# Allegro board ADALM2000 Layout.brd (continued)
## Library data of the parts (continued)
C8 C14 C20-C22 C24-C28 C94 C217 C218 C258-C261 C270 C271 C281 C302-C305 C314 C315 C596 C607 C615 C639 C641 C665 C666 C672 C675 C679 C698-C701 C789 = CAP: Tolerance: 10; User Part Number: UPN; alternate symbols: C0402L_ALT; part number: CAP_SM-4.7UF,10V,10,E022491,C0402; tolerance: 10
C9-C12 = CAP: Tolerance: 20; User Part Number: UPN; alternate symbols: (); part number: CAP_SM-47UF,10V,20,E020003,C1206H71; tolerance: 20
C13 C34-C43 C45 C46 C48 C70 C78 C83 C84 C93 C102 C117-C120 C127 C135 C140 C141 C149 C153 C168-C171 C188 C225 C227 C233-C235 C253 C254 C268 C269 C276 C277 C282 C283 C290 C295 C298 C301 C309 C322 C323 C328 C332 C335 C599 C633 C644 C648 C650 C654 C660 C692 C712 C713 C793 C803 = CAP: User Part Number: UPN; Tolerance: 10; alternate symbols: (); part number: CAP_SM-0.01UF,25V,10,E022720,C0201; tolerance: 10
C15 = CAP: Tolerance: 10; User Part Number: UPN; alternate symbols: C0402L_ALT; part number: CAP_SM-15NF,35V,10,E033385,C0402; tolerance: 10
C17 C122 C173 = CAP: Tolerance: 5; User Part Number: UPN; alternate symbols: C0402L_ALT; part number: CAP_SM-10PF,50V,5,E007982,C0402; tolerance: 5
C18 C105 C106 C154 C155 C176 C178 C183 C187 C190 C226 C230 C242 C243 C278 C279 C289 C291 C312 C313 C325 C326 C656 C659 C662 C737 C738 C740 C742 C769 C774 = CAP: Tolerance: 20; User Part Number: UPN; alternate symbols: C0603L_ALT; part number: CAP_SM-10UF,10V,20,E022682,C0603; tolerance: 20
C23 C99 = CAP: User Part Number: UPN; Tolerance: 20; alternate symbols: C0805-2; part number: CAP_SM-22UF,25V,20,E032575,C0805H60; tolerance: 20
C52 = CAP: Tolerance: 10; User Part Number: UPN; alternate symbols: C0402L_ALT; part number: CAP_SM-1000PF,25V,10,E025706,C0402; tolerance: 10
C63 C657 = CAP: Tolerance: 10; User Part Number: UPN; alternate symbols: C0402L_ALT; part number: CAP_SM-0.22UF,16V,10,E032715,C0402; tolerance: 10
C64 = CAP: Tolerance: 5; User Part Number: UPN; alternate symbols: C0402L_ALT; part number: CAP_SM-820PF,25V,5,E012598,C0402; tolerance: 5
C66 = CAP: Tolerance: 10; User Part Number: UPN; alternate symbols: C0402L_ALT; part number: CAP_SM-0.068UF,10V,10,E033177,C0402H22; tolerance: 10
C69 C71 C126 C128 = CAPVAR: Tolerance: N/A; User Part Number: UPN; alternate symbols: (); part number: CAPVAR_SM-5-20PF,100V,N/A,E023860,CSML177W126H67; tolerance: N/A
C72 C75 C129 C132 C182 C197 = CAP: Tolerance: 5; User Part Number: UPN; alternate symbols: C0603L_ALT; part number: CAP_SM-33PF,50V,5,E000396,C0603; tolerance: 5
C73 C76 C95 C130 = CAP: Tolerance: 5; User Part Number: UPN; alternate symbols: C0603L_ALT; part number: CAP_SM-82PF,50V,5,E000414,C0603; tolerance: 5
C74 C77 C131 C134 = CAP: Tolerance: 2; User Part Number: UPN; alternate symbols: C0603L_ALT; part number: CAP_SM-0.001UF,50V,2,E022455,C0603; tolerance: 2
C85 C88 C143 C145 C236 C237 = CAP: Tolerance: 5; User Part Number: UPN; alternate symbols: C0402L_ALT; part number: CAP_SM-100PF,50V,5,E024302,C0402; tolerance: 5; signal model: capacitor20pF
C89 C92 C146 C147 C751 = CAP: Tolerance: 5; User Part Number: UPN; alternate symbols: C0402L_ALT; part number: CAP_SM-150PF,50V,5,E012646,C0402; tolerance: 5
C101 = CAP: Tolerance: 20; User Part Number: UPN; alternate symbols: C0805-2; part number: CAP_SM-22UF,25V,20,E032575,C0805H60; tolerance: 20
C103 C104 C121 C123 C162 C163 C172 C174 C266 C267 = CAP: Tolerance: 0.1pF; User Part Number: UPN; alternate symbols: C0402L_ALT; part number: CAP_SM-1PF,25V,0.1PF,E011093,C0402; tolerance: 0.1pF
C181 C189 C337 C339 = CAP: User Part Number: UPN; Tolerance: 0.05PF; alternate symbols: (); part number: CAP_SM-3PF,50V,0.05PF,E033791,C0402; tolerance: 0.05PF
C184 C238 = CAP: Tolerance: 5; User Part Number: UPN; alternate symbols: C0402L_ALT; part number: CAP_SM-220PF,50V,5,E018153,C0402; tolerance: 5
C185 C336 C338 C340 = CAP: User Part Number: UPN; Tolerance: 0.25PF; alternate symbols: (); part number: CAP_SM-1PF,50V,0.25PF,E000276,C0402; tolerance: 0.25PF
C193 C194 C745 C746 = CAP: Tolerance: 10; User Part Number: UPN; alternate symbols: C0402L_ALT; part number: CAP_SM-0.047UF,25V,10,E025704,C0402; tolerance: 10
C199 = CAP: Tolerance: 5; User Part Number: UPN; alternate symbols: C0402L_ALT; part number: CAP_SM-120PF,25V,5,E012600,C0402; tolerance: 5
C200 C201 = CAP: Tolerance: 10; User Part Number: UPN; alternate symbols: C0402L_ALT; part number: CAP_SM-0.018UF,16V,10,E019653,C0402; tolerance: 10
C203 = CAP: Tolerance: 10; User Part Number: UPN; alternate symbols: C0402L_ALT; part number: CAP_SM-0.0022UF,50V,10,E007460,C0402; tolerance: 10
C207 = CAP: Tolerance: 5; User Part Number: UPN; alternate symbols: C0402L_ALT; part number: CAP_SM-0.0012UF,25V,5,E012597,C0402; tolerance: 5
C208 C241 C320 C321 C664 C678 C680 C696 C697 C754 C758 C761 C762 = CAP: Tolerance: 20; User Part Number: UPN; alternate symbols: (C0805L); part number: CAP_SM-47UF,6.3V,20,E008247,C0805H60; tolerance: 20
C223 = CAP: User Part Number: UPN; Tolerance: 1; alternate symbols: (); part number: CAP_SM-12PF,50V,1,E033792,C0402; tolerance: 1
C239 = CAP: Tolerance: 0.05pF; User Part Number: UPN; alternate symbols: C0402L_ALT; part number: CAP_SM-4.7PF,50V,0.05PF,E021938,C0402; tolerance: 0.05pF
C248 C249 C252 C255-C257 = CAP: Tolerance: 0.1pF; User Part Number: UPN; alternate symbols: C0402L_ALT; part number: CAP_SM-3.9PF,50V,0.1PF,E014597,C0402; tolerance: 0.1pF
C280 C801 = CAP: Tolerance: 10; User Part Number: UPN; alternate symbols: C0402L_ALT; part number: CAP_SM-2.2UF,10V,10,E017584,C0402; tolerance: 10
C327 C329 = CAP: User Part Number: UPN; Tolerance: 20; alternate symbols: C0402L_ALT; part number: CAP_SM-1UF,16V,20,E020695,C0402; tolerance: 20
C579 C588 C589 C598 C626 C647 C649 C651 C652 C655 C658 C688 C710 C711 C792 C795 = CAP: User Part Number: UPN; Tolerance: 20; part number: CAP_SM-0.1UF,16V,20,E017331,C0201; tolerance: 20
C595 C600 C637 C663 C670 C676 C788 = CAP: Tolerance: 20; User Part Number: UPN; alternate symbols: (); part number: CAP_SM-100UF,6.3V,20,E016591,C1206H71; tolerance: 20
C597 C614 C616-C618 C643 C645 C667-C669 C671 C673 C674 C683 C684 C686 C702-C709 C790 = CAP: Tolerance: 10; User Part Number: UPN; alternate symbols: C0402L_ALT; part number: CAP_SM-0.47UF,10V,10,E007611,C0402; tolerance: 10
C753 = CAP: Tolerance: 5; User Part Number: UPN; alternate symbols: C0402L_ALT; part number: CAP_SM-5.6NF,50V,5,E033450,C0402H22; tolerance: 5
C756 = CAP: Tolerance: 5; User Part Number: UPN; alternate symbols: C0402L_ALT; part number: CAP_SM-180PF,50V,5,E033222,C0402; tolerance: 5
C757 = CAP: Tolerance: 10; User Part Number: UPN; alternate symbols: C0402L_ALT; part number: CAP_SM-0.0033UF,50V,10,E007461,C0402; tolerance: 10
CALIB_REF1 CALIB_REF2 GND_7-GND_10 IO3 RX TCK TDI TDO TMS TX UNK1V8_D UNK1V35 UNK3V3_A UNK3V3_D UNK4V0_A UNK6V0_A UNK-3V3_A UNK-6V0_A VCCPINT VIN = NCTESTPAD: Tolerance: N/A; User Part Number: UPN; alternate symbols: (); part number: NCTESTPAD_SM-TESTPAD,E019801,TPSMC40; tolerance: N/A
D1 D26 = DIOZNR: User Part Number: UPN; Tolerance: 5; alternate symbols: (); part number: DIOZNR_SM-SMBJ5340B-TP,6V,5,E029884,DO214AA; tolerance: 5
D2-D23 = DIO3P_V3: Tolerance: N/A; User Part Number: UPN; alternate symbols: (); part number: DIO3P_V3_SM-DB3S406F0L,40V,N/A,E023784,SC89; tolerance: N/A
D24 = DIOSCHOTTKY: Tolerance: N/A; User Part Number: UPN; alternate symbols: (); part number: DIOSCHOTTKY_SM-PD3S140-7,60V,N/A,E017965,POWERDI323; tolerance: N/A
D25 = DIOSCHOTTKY: User Part Number: UPN; Tolerance: N/A; alternate symbols: (); part number: DIOSCHOTTKY_SM-MBR130LSFT1G,30V,N/A,E016634,SOD123FL; tolerance: N/A
D739 D741 = DIO: Tolerance: N/A; User Part Number: UPN; alternate symbols: (); part number: DIO_SM-SESD0201X1UN-0020-09,9V,N/A,E022225,D0201; tolerance: N/A
DS11 DS12 = DIOLED: User Part Number: UPN; Tolerance: N/A; alternate symbols: LED0804_RA; part number: DIOLED_SM-LTST-S220TBKT,3.3V,N/A,E026167,LED0804; tolerance: N/A
E1-E3 E5 E8-E10 E12-E19 E22 E24 = FERRITE: Tolerance: 25; User Part Number: UPN; alternate symbols: (); part number: FERRITE_SM-220OHM,25,E016865,L0402; tolerance: 25
E4 E21 E26 E682 E687 E767 E768 = FERRITE: Tolerance: 25; User Part Number: UPN; alternate symbols: (); part number: FERRITE_SM-100OHM,25,E012241,L0805; tolerance: 25
E677 = FERRITE: Tolerance: 25; User Part Number: UPN; alternate symbols: (); part number: FERRITE_SM-600OHMS,25,E007179,L0603; tolerance: 25
F1 = FSFUSE: User Part Number: UPN; Tolerance: N/A; alternate symbols: (); part number: FSFUSE_SM-0.5A,6V,E016128,F0805; tolerance: N/A
GND_4-GND_6 OFF_SC1 OFF_SC2 TP5-TP7 = NCTESTPAD: Tolerance: N/A; User Part Number: UPN; alternate symbols: (); part number: NCTESTPAD_TH-TESTPAD,E007450,TPC50D30; tolerance: N/A
L1 = CHOKE4P: User Part Number: UPN; Tolerance: 25; alternate symbols: (); part number: CHOKE4P_SM-90OHMS AT 100MEGHZ,25,E027226,L0805-4PH39; tolerance: 25
L2 = IND: User Part Number: UPN; Tolerance: 30; alternate symbols: (); part number: IND_SM-3UH,30,E026905,LSMSQ228H118_A; tolerance: 30
L3 = IND: User Part Number: UPN; Tolerance: N/A; alternate symbols: (); part number: IND_SM-10UH,N/A,E021217,LSMSQ287H161_A; tolerance: N/A
L4 = IND: User Part Number: UPN; Tolerance: 20; alternate symbols: (); part number: IND_SM-180NH,20,E026052,LSMSQ79H41; tolerance: 20
L5 = IND: User Part Number: UPN; Tolerance: 20; alternate symbols: (); part number: IND_SM-600NH,20,E020702,LSMSQ157H47; tolerance: 20
L6 = IND: User Part Number: UPN; Tolerance: 20; alternate symbols: (); part number: IND_SM-4.7UH,20,E013623,LSMSQ157H122; tolerance: 20
L7 = IND: Tolerance: 5; User Part Number: UPN; alternate symbols: (); part number: IND_SM-110NH,5,E016398,L9075; tolerance: 5
L8 = IND: User Part Number: UPN; Tolerance: 20; alternate symbols: (); part number: IND_SM-5.6UH,20,E027225,LSMSQ154H47_A; tolerance: 20
L9 = IND: User Part Number: UPN; Tolerance: 20; alternate symbols: (); part number: IND_SM-1UH,20,E015845,LSMSQ157H83; tolerance: 20
L10 = CHOKE4P: User Part Number: UPN; Tolerance: N/A; alternate symbols: (); part number: CHOKE4P_SM-190OHMS AT 100MEGHZ,N/A,E019844,L2020_A; tolerance: N/A
L13 L14 = IND: Tolerance: 2; User Part Number: UPN; alternate symbols: (); part number: IND_SM-270NH,2,E010087,L7144; tolerance: 2
L15 L16 = IND: Tolerance: 2; User Part Number: UPN; alternate symbols: (); part number: IND_SM-220NH,2,E024706,L7144; tolerance: 2
L520 L521 = IND: User Part Number: UPN; Tolerance: 20; alternate symbols: (); part number: IND_SM-1.5UH,20,E017267,LSMSQ157H83; tolerance: 20
P1 = CN30P_ODD_EVEN_V2: User Part Number: UPN; Tolerance: N/A; alternate symbols: (); part number: CN30P_ODD_EVEN_V2_TH-TSW-115-08-F-D-RA,E021381,CNHDRRA2X15H224; tolerance: N/A
P510 = CN10P_ODD_EVEN: Tolerance: N/A; User Part Number: UPN; part number: CN10P_ODD_EVEN_TH-FTSH-105-01-L-D,E018623,CNHDR2X5H219; tolerance: N/A
P516 P519 = CN5P_3SHLD: User Part Number: UPN; Tolerance: N/A; alternate symbols: (); part number: CN5P_3SHLD_SM-47590-0001,E015753,CNMOLEX47590-0001; tolerance: N/A
Q1 Q2 Q512 = TRANNMOSFET_V8: User Part Number: UPN; Tolerance: N/A; part number: TRANNMOSFET_V8_SM-BSS138LT1G,E018770,SOT23; tolerance: N/A
Q3-Q5 = TRANIRLMLXXXX: User Part Number: UPN; Tolerance: N/A; alternate symbols: (); part number: TRANIRLMLXXXX_SM-IRLML5103TRPBF,E010204,SOT23-M3; tolerance: N/A
Q8 Q9 = TRANNMOSFET_V8: User Part Number: UPN; Tolerance: N/A; alternate symbols: (); part number: TRANNMOSFET_V8_SM-BSS123LT1G,E022331,SOT23; tolerance: N/A
R1 R766 = RES: Tolerance: 1; User Part Number: UPN; alternate symbols: R0402L_ALT; part number: RES_SM-23.2K,E019517,1/16W,1,R0402; tolerance: 1
R2 R89 = RES: Tolerance: 1; User Part Number: UPN; alternate symbols: R0402L_ALT; part number: RES_SM-100K,E003796,1/16W,1,R0402; tolerance: 1
R3 R4 R13 R14 R24 R25 R47 R50 R51 R87 R116 R119 R120 R130 R140-R142 R144 R156 R195 R196 R201 R202 R212 R638 R640 R752 R760 R791 = RES: Tolerance: 1; User Part Number: UPN; alternate symbols: R0402L_ALT; part number: RES_SM-10K,E003751,1/10W,1,R0402; tolerance: 1
R6 R74 R75 = RES: Tolerance: 1; User Part Number: UPN; alternate symbols: R0402L_ALT; part number: RES_SM-8.25K,E013600,1/10W,1,R0402; tolerance: 1
R7 = RES: Tolerance: 1; User Part Number: UPN; alternate symbols: R0402L_ALT; part number: RES_SM-10.7K,E019637,1/16W,1,R0402; tolerance: 1
R8 R11 R12 R76 R91 R97 R98 R149-R153 R205 R206 R209 R216 R217 R587 R642 R653 R681 = RES: Tolerance: 5; User Part Number: UPN; alternate symbols: R0402L_ALT; part number: RES_SM-0,E003438,N/A,5,R0402; tolerance: 5
R9 = RES: Tolerance: 1; User Part Number: UPN; alternate symbols: R0402L_ALT; part number: RES_SM-2,E022716,1/16W,1,R0402; tolerance: 1
R10 = RES: Tolerance: 1; User Part Number: UPN; alternate symbols: R0402L_ALT; part number: RES_SM-90.9K,E019943,1/10W,1,R0402; tolerance: 1
R15 = RES: User Part Number: UPN; Tolerance: 1; alternate symbols: (); part number: RES_SM-22,E024499,1/20W,1,R0201; tolerance: 1
R16 R19 R41 R44 = RES: Tolerance: 1; User Part Number: UPN; alternate symbols: (R0805L); part number: RES_SM-820K,E005793,1/8W,1,R0805; tolerance: 1
R17 R20 R42 R45 = RES: Tolerance: 1; User Part Number: UPN; alternate symbols: R0603L; part number: RES_SM-200K,E015343,1/10W,1,R0603; tolerance: 1
R18 R21 R43 R46 = RES: Tolerance: 1; User Part Number: UPN; alternate symbols: R0603L; part number: RES_SM-21K,E021794,1/10W,1,R0603; tolerance: 1
R22 R23 R32 R33 R48 R49 R58 R59 R148 R204 = RES: Tolerance: 1; User Part Number: UPN; alternate symbols: R0402L_ALT; part number: RES_SM-4.99K,E006643,1/16W,1,R0402; tolerance: 1
R26 R27 R52 R53 = RES: Tolerance: 1; User Part Number: UPN; alternate symbols: R0402L_ALT; part number: RES_SM-3K,E022429,1/10W,1,R0402; tolerance: 1
R28 R29 R34 R35 R54 R55 R60 R61 R121 R122 = RES: Tolerance: 1; User Part Number: UPN; alternate symbols: R0402L_ALT; part number: RES_SM-3.9K,E014697,1/10W,1,R0402; tolerance: 1
R30 R31 R56 R57 = RES: Tolerance: 0.1; User Part Number: UPN; alternate symbols: R0402L_ALT; part number: RES_SM-11.3K,E019952,1/16W,0.1,R0402; tolerance: 0.1
R36 R62 R581 R797 = RES: Tolerance: 1; User Part Number: UPN; alternate symbols: R0402L_ALT; part number: RES_SM-33,E020519,1/10W,1,R0402; tolerance: 1
R37 R38 R63 R64 = RES: Tolerance: 1; User Part Number: UPN; alternate symbols: R0402L_ALT; part number: RES_SM-100,E003760,1/16W,1,R0402; tolerance: 1; signal model: resistor50
R39 R40 R65 R66 = RES: Tolerance: 1; User Part Number: UPN; alternate symbols: R0402L_ALT; part number: RES_SM-4.99,E016554,1/16W,1,R0402; tolerance: 1
R67 = RES: Tolerance: 0.1; User Part Number: UPN; alternate symbols: R0402L_ALT; part number: RES_SM-3.83K,E020197,1/16W,0.1,R0402; tolerance: 0.1
R68 = RES: Tolerance: 5; User Part Number: UPN; alternate symbols: R0402L_ALT; part number: RES_SM-1,E010031,1/16W,5,R0402; tolerance: 5
R69 = RES: Tolerance: 1; User Part Number: UPN; alternate symbols: R0402L_ALT; part number: RES_SM-43.2K,E018504,1/10W,1,R0402; tolerance: 1
R70 = RES: Tolerance: 1; User Part Number: UPN; alternate symbols: R0603L; part number: RES_SM-35.7K,E016592,1/10W,1,R0603; tolerance: 1
R71 = RES: Tolerance: 1; User Part Number: UPN; alternate symbols: R0402L_ALT; part number: RES_SM-9.09K,E003770,1/16W,1,R0402; tolerance: 1
R72 = RES: Tolerance: 1; User Part Number: UPN; alternate symbols: R0402L_ALT; part number: RES_SM-105K,E019614,1/16W,1,R0402; tolerance: 1
R73 = RES: Tolerance: 1; User Part Number: UPN; alternate symbols: R0402L_ALT; part number: RES_SM-165K,E026053,1/16W,1,R0402; tolerance: 1
R77 = RES: Tolerance: 1; User Part Number: UPN; alternate symbols: R0402L_ALT; part number: RES_SM-69.8K,E019611,1/16W,1,R0402; tolerance: 1
R78 = RES: Tolerance: 1; User Part Number: UPN; alternate symbols: R0402L_ALT; part number: RES_SM-120K,E015615,1/10W,1,R0402; tolerance: 1
R79 = RES: Tolerance: 0.1; User Part Number: UPN; alternate symbols: R0402L_ALT; part number: RES_SM-1.6K,E016212,0.063W,0.1,R0402; tolerance: 0.1
R80 R82 = RES: Tolerance: 0.1; User Part Number: UPN; alternate symbols: R0402L_ALT; part number: RES_SM-1K,E005978,1/16W,0.1,R0402; tolerance: 0.1
R81 = RES: Tolerance: 0.1; User Part Number: UPN; alternate symbols: R0402L_ALT; part number: RES_SM-4.02K,E011895,1/16W,0.1,R0402; tolerance: 0.1
R83 R84 R101 R103 R192 R215 R691 = RES: Tolerance: 1; User Part Number: UPN; alternate symbols: R0402L_ALT; part number: RES_SM-470,E014032,1/16W,1,R0402; tolerance: 1
R85 R210 R211 R685 R689 R747 = RES: Tolerance: 1; User Part Number: UPN; alternate symbols: R0402L_ALT; part number: RES_SM-4.7K,E008190,1/10W,1,R0402; tolerance: 1
R86 = RES: Tolerance: 1; User Part Number: UPN; alternate symbols: R0402L_ALT; part number: RES_SM-22K,E018369,1/16W,1,R0402; tolerance: 1
R88 R517 = RES: User Part Number: UPN; Tolerance: 1; part number: RES_SM-10,E013982,1/20W,1,R0201; tolerance: 1
R90 R164 = RES: Tolerance: 1; User Part Number: UPN; alternate symbols: R0402L_ALT; part number: RES_SM-15K,E007441,1/16W,1,R0402; tolerance: 1
R92 = RES: Tolerance: 1; User Part Number: UPN; alternate symbols: R0402L_ALT; part number: RES_SM-82.5K,E025324,1/16W,1,R0402; tolerance: 1
R93-R96 = RES: Tolerance: 1; User Part Number: UPN; alternate symbols: R0603L; part number: RES_SM-124,E004853,1/10W,1,R0603; tolerance: 1
R99 R100 = RES: Tolerance: 1; User Part Number: UPN; alternate symbols: R0603L; part number: RES_SM-3K,E013586,1/10W,1,R0603; tolerance: 1
R102 R104 = RES: Tolerance: 1; User Part Number: UPN; alternate symbols: R0402L_ALT; part number: RES_SM-100,E016329,1/10W,1,R0402; tolerance: 1
R105 R106 R117 R118 R123 R124 = RES: Tolerance: 1; User Part Number: UPN; alternate symbols: R0603L; part number: RES_SM-1.47K,E007637,0.1W,1,R0603; tolerance: 1
R107 R108 = RES: Tolerance: 1; User Part Number: UPN; alternate symbols: R0402L_ALT; part number: RES_SM-2.21K,E003783,1/16W,1,R0402; tolerance: 1
R109-R114 R167-R188 = RES: User Part Number: UPN; Tolerance: 1; alternate symbols: (); part number: RES_SM-22,E024499,1/20W,1,R0201; tolerance: 1; signal model: resistor50
R115 R136 = RES: Tolerance: 1; User Part Number: UPN; alternate symbols: R0402L_ALT; part number: RES_SM-2K,E003752,1/16W,1,R0402; tolerance: 1
R125 R126 = RES: Tolerance: 1; User Part Number: UPN; alternate symbols: R0402L_ALT; part number: RES_SM-1.3K,E015613,1/10W,1,R0402; tolerance: 1
R127 R128 R213 = RES: Tolerance: 1; User Part Number: UPN; alternate symbols: R0402L_ALT; part number: RES_SM-2.49K,E007345,1/10W,1,R0402; tolerance: 1
R129 R131 R145 R147 R154 R199 R200 R214 R583-R585 R590-R594 R750 R798 = RES: Tolerance: 1; User Part Number: UPN; alternate symbols: R0402L_ALT; part number: RES_SM-20K,E003791,1/16W,1,R0402; tolerance: 1
R132 R133 = RES: Tolerance: 1; User Part Number: UPN; alternate symbols: (); part number: RES_SM-49.9,E003114,1/4W,1,R1206; tolerance: 1
R134 R135 R190 R800 = RES: Tolerance: 1; User Part Number: UPN; alternate symbols: R0402L_ALT; part number: RES_SM-8.06K,E021385,1/10W,1,R0402; tolerance: 1
R137-R139 R161 = RES: Tolerance: 1; User Part Number: UPN; alternate symbols: R0402L_ALT; part number: RES_SM-4.02K,E004026,1/16W,1,R0402; tolerance: 1
R143 R189 = RES: Tolerance: 1; User Part Number: UPN; alternate symbols: R0402L_ALT; part number: RES_SM-100,E003760,1/16W,1,R0402; tolerance: 1
R155 = RES: Tolerance: 1; User Part Number: UPN; alternate symbols: (); part number: RES_SM-4.7K,E008190,1/10W,1,R0402; tolerance: 1
R158 R159 R197 R198 R636 = RES: Tolerance: 1; User Part Number: UPN; alternate symbols: R0402L_ALT; part number: RES_SM-1K,E003763,1/10W,1,R0402; tolerance: 1
R160 = RES: Tolerance: 0.1; User Part Number: UPN; alternate symbols: R0402L_ALT; part number: RES_SM-5.1K,E010267,1/16W,0.1,R0402; tolerance: 0.1
R162 R163 = RES: Tolerance: 5; User Part Number: UPN; alternate symbols: (R0805L); part number: RES_SM-4.7,E004023,1/8W,5,R0805; tolerance: 5
R165 = RES: Tolerance: 1; User Part Number: UPN; alternate symbols: (R0402L); part number: RES_SM-6.49K,E026140,1/10W,1,R0402; tolerance: 1
R166 R743 = RES: Tolerance: 1; User Part Number: UPN; alternate symbols: R0402L_ALT; part number: RES_SM-27.4K,E021819,1/10W,1,R0402; tolerance: 1
R191 R586 R634 R635 R661 = RES: Tolerance: 1; User Part Number: UPN; alternate symbols: R0402L_ALT; part number: RES_SM-240,E010877,1/16W,1,R0402; tolerance: 1
R193 R194 = RES: Tolerance: 1; User Part Number: UPN; alternate symbols: R0402L_ALT; part number: RES_SM-11K,E015614,1/10W,1,R0402; tolerance: 1
R203 = RES: Tolerance: 1; User Part Number: UPN; alternate symbols: R0402L_ALT; part number: RES_SM-47.5K,E013598,1/10W,1,R0402; tolerance: 1
R207 = RES: Tolerance: 1; User Part Number: UPN; alternate symbols: R0402L_ALT; part number: RES_SM-16.2K,E022435,1/10W,1,R0402; tolerance: 1
R208 = RES: Tolerance: 1; User Part Number: UPN; alternate symbols: R0402L_ALT; part number: RES_SM-24.3K,E024557,1/16W,1,R0402; tolerance: 1
R601-R606 R608-R613 R619-R624 R627-R632 = RES: User Part Number: UPN; Tolerance: 1; part number: RES_SM-120,E011549,1/20W,1,R0201; tolerance: 1
R625 = RES: Tolerance: 0.1; User Part Number: UPN; alternate symbols: R0402L_ALT; part number: RES_SM-80.6,E022369,1/16W,0.1,R0402; tolerance: 0.1
R744 R749 = RES: Tolerance: 1; User Part Number: UPN; alternate symbols: (R0402L,R0402L_ALT); part number: RES_SM-1K,E003763,1/10W,1,R0402; tolerance: 1
R763 = RES: Tolerance: 1; User Part Number: UPN; alternate symbols: R0603L; part number: RES_SM-17.8K,E011033,1/10W,1,R0603; tolerance: 1
R764 = RES: User Part Number: UPN; Tolerance: 1; part number: RES_SM-14.3K,E014068,1/20W,1,R0201; tolerance: 1
R765 = RES: Tolerance: 1; User Part Number: UPN; alternate symbols: R0402L_ALT; part number: RES_SM-46.4K,E011115,1/16W,1,R0402; tolerance: 1
RT1-RT18 = RESTHERM: Tolerance: N/A; User Part Number: UPN; alternate symbols: (); part number: RESTHERM_SM-220,E023781,N/A,N/A,R0603H35; tolerance: N/A
S1 = SWSPST5P_V2: User Part Number: UPN; Tolerance: N/A; alternate symbols: (); part number: SWSPST5P_V2_SM-PTS840 GKP SMTR LFS,E024294,SWSML140W138H55; tolerance: N/A
U2 = AD9963: User Part Number: UPN; Tolerance: N/A; alternate symbols: (); part number: AD9963_SM-AD9963BCPZ,E023805,QFN72_10X10_PAD7_1X7_1; tolerance: N/A
U3 U4 = ADA4940_2_V2: User Part Number: UPN; Tolerance: N/A; alternate symbols: (); part number: ADA4940_2_V2_SM-ADA4940-2ACPZ,E017451,QFN24_4X4_PAD2_5X2_5; tolerance: N/A
U6 U518 = ADP2114: User Part Number: UPN; Tolerance: N/A; alternate symbols: (); part number: ADP2114_SM-ADP2114ACPZ,E008105,QFN32_5X5_PAD3_1X3_1; tolerance: N/A
U7 = ADP237X: Tolerance: N/A; User Part Number: UPN; alternate symbols: (); part number: ADP237X_SM-ADP2370ACPZ-R7,E016641,QFN8_3X3_PAD2_44X1_7; tolerance: N/A
U8 U9 = ADG1404_V2: Tolerance: N/A; User Part Number: UPN; alternate symbols: (); part number: ADG1404_V2_SM-ADG1404YCPZ,E029836,QFN16_4X4_PAD2_5X2_5; tolerance: N/A
U10 = ADP5074: Tolerance: N/A; User Part Number: UPN; alternate symbols: (); part number: ADP5074_SM-ADP5074ACPZ,E023965,QFN16_3X3_PAD1_7X1_7; tolerance: N/A
U11 = AD56X5: Tolerance: N/A; User Part Number: UPN; alternate symbols: (); part number: AD56X5_SM-AD5625BRUZ,E024850,TSSOP14; tolerance: N/A
U12 = ADP1614: User Part Number: UPN; Tolerance: N/A; alternate symbols: (); part number: ADP1614_SM-ADP1614ACPZ,E025247,QFN10_3X3_PAD2_38X1_64; tolerance: N/A
U13 = ADP7182_V2: Tolerance: N/A; User Part Number: UPN; alternate symbols: (); part number: ADP7182_V2_SM-ADP7182ACPZ-R7,E017567,QFN8_3X3_PAD2_44X1_7; tolerance: N/A
U14 = ADF4360_9: User Part Number: UPN; Tolerance: N/A; alternate symbols: (); part number: ADF4360_9_SM-ADF4360-9BCPZ,E023893,QFN24_4X4_PAD2_3X2_3; tolerance: N/A
U15 = ADP5589_V2: Tolerance: N/A; User Part Number: UPN; alternate symbols: (); part number: ADP5589_V2_SM-ADP5589ACPZ-00,E024896,QFN24_3_5X3_5_PAD2_2X2_2; tolerance: N/A
U16 = ADP198: Tolerance: N/A; User Part Number: UPN; alternate symbols: (); part number: ADP198_SM-ADP198ACBZ-11,E024730,WLCSP4-2; tolerance: N/A
U17 = LINLT1761: User Part Number: UPN; Tolerance: N/A; alternate symbols: (); part number: LINLT1761_SM-LT1761ES5-SD#TRMPBF,E031208,TSOT-5; tolerance: N/A
U18 U19 = ADR34XX: User Part Number: UPN; Tolerance: N/A; alternate symbols: (); part number: ADR34XX_SM-ADR3412ARJZ,E015880,SOT23_6-2; tolerance: N/A
U20 = AD56X7: Tolerance: N/A; User Part Number: UPN; alternate symbols: (); part number: AD56X7_SM-AD5627BRMZ,E024847,RM10; tolerance: N/A
U21 = LINLTC4415: User Part Number: UPN; Tolerance: N/A; alternate symbols: (); part number: LINLTC4415_SM-LTC4415EDHC#PBF,E027541,DFN16_5X3_PAD4_4X1_65; tolerance: N/A
U508 = ICMT25Q: User Part Number: UPN; Tolerance: N/A; alternate symbols: (); part number: ICMT25Q_SM-MT25QU256ABA8E12-1SIT,E027529,TBGA24; tolerance: N/A
U509 = ICTPS51206: Tolerance: N/A; User Part Number: UPN; alternate symbols: (); part number: ICTPS51206_SM-TPS51206DSQR,E021346,SON10_2X2_PAD1_5X0_9; tolerance: N/A
U511 = ICXC7Z010: Tolerance: N/A; User Part Number: UPN; alternate symbols: (); part number: ICXC7Z010_SM-XC7Z010-1CLG225C4334,E025809,CSPBGA225; tolerance: N/A
U524 = ICUSB3320C: Tolerance: N/A; User Part Number: UPN; alternate symbols: (); part number: ICUSB3320C_SM-USB3320C-EZK,E021334,QFN32_5X5_PAD3_3X3_3; tolerance: N/A
U646 = ICMT41K256M16: User Part Number: UPN; Tolerance: N/A; alternate symbols: (); part number: ICMT41K256M16_SM-MT41K256M16TW-107:P,E025442,FBGA96_C; tolerance: N/A
VR1 = LINLT1964_5: User Part Number: UPN; Tolerance: N/A; alternate symbols: (); part number: LINLT1964_5_SM-LT1964ES5-5#TRPBF,E013330,TSOT-5; tolerance: N/A
Y1 = XTALOSC4P_V9: Tolerance: N/A; User Part Number: UPN; alternate symbols: (); part number: XTALOSC4P_V9_SM-20MHZ,E024704,YSML197W126H59-2; tolerance: N/A
Y523 = XTALOSC4P_V7: Tolerance: N/A; User Part Number: UPN; alternate symbols: (); part number: XTALOSC4P_V7_SM-24MEGHZ,E022374,YSML98W79H35; tolerance: N/A
Y578 = XTALOSC4P_V7: Tolerance: N/A; User Part Number: UPN; part number: XTALOSC4P_V7_SM-33.333MEGHZ,E024048,YSML98W79H35; tolerance: N/A

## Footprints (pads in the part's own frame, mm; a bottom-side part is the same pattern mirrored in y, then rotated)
C0201
  rect 0.305x0.406 smd: 1(-0.318,0) 2(0.318,0)
C0402
  rect 0.483x0.559 smd: 1(-0.438,0) 2(0.438,0)
C0402#2
  rect 0.584x0.66 smd: 1(-0.5,0) 2(0.5,0)
C0402H22
  rect 0.483x0.559 smd: 1(-0.438,0) 2(0.438,0)
C0603
  rect 0.762x0.889 smd: 1(-0.699,0) 2(0.699,0)
C0603#2
  rect 1.092x1.194 smd: 1(-0.851,0) 2(0.851,0)
C0805H60
  rect 1.295x1.6 smd: 1(-0.953,0) 2(0.953,0)
C1206H71
  rect 1.6x2.007 smd: 1(-1.397,0) 2(1.397,0)
CNHDR2X5H219
  rect 1.067x1.067 hole 0.711: 1(0,0)
  round 1.067 hole 0.711: 2(0,1.27) 3(1.27,0) 4(1.27,1.27) 5(2.54,0) 6(2.54,1.27) 7(3.81,0) 8(3.81,1.27) 9(5.08,0) 10(5.08,1.27)
CNHDRRA2X15H224
  rect 1.651x1.651 hole 1.143: 1(0,0)
  round 1.651 hole 1.143: 2(0,2.54) 3(2.54,0) 4(2.54,2.54) 5(5.08,0) 6(5.08,2.54) 7(7.62,0) 8(7.62,2.54) 9(10.16,0) 10(10.16,2.54) 11(12.7,0) 12(12.7,2.54) 13(15.24,0) 14(15.24,2.54) 15(17.78,0) 16(17.78,2.54) 17(20.32,0) 18(20.32,2.54) 19(22.86,0) 20(22.86,2.54) 21(25.4,0) 22(25.4,2.54) 23(27.94,0) 24(27.94,2.54) 25(30.48,0) 26(30.48,2.54) 27(33.02,0) 28(33.02,2.54) 29(35.56,0) 30(35.56,2.54)
CNMOLEX47590-0001
  oval 1.118x0.914 hole 0.864x0.66: (4.45,2.225) (4.45,-2.225)
  rect 1.346x0.406 smd: 1(4.123,-1.3) 2(4.123,-0.65) 3(4.123,0) 4(4.123,0.65) 5(4.123,1.3)
  custom 0.349x0.349 hole 1.295x0.61: SH1(1.45,4.175) SH3(1.45,-4.175)
  rect 1.905x2.896 smd: SH2(1.45,0)
CSML177W126H67
  rect 0.838x0.991 smd: 1(-2.069,0) 2(2.069,0)
CSPBGA225
  round 0.305 smd: A1(-5.6,-5.6) A2(-5.6,-4.8) A3(-5.6,-4) A4(-5.6,-3.2) A5(-5.6,-2.4) A6(-5.6,-1.6) A7(-5.6,-0.8) A8(-5.6,0) A9(-5.6,0.8) A10(-5.6,1.6) A11(-5.6,2.4) A12(-5.6,3.2) A13(-5.6,4) A14(-5.6,4.8) A15(-5.6,5.6) B1(-4.8,-5.6) B2(-4.8,-4.8) B3(-4.8,-4) B4(-4.8,-3.2) B5(-4.8,-2.4) B6(-4.8,-1.6) B7(-4.8,-0.8) B8(-4.8,0) B9(-4.8,0.8) B10(-4.8,1.6) B11(-4.8,2.4) B12(-4.8,3.2) B13(-4.8,4) B14(-4.8,4.8) B15(-4.8,5.6) C1(-4,-5.6) C2(-4,-4.8) C3(-4,-4) C4(-4,-3.2) C5(-4,-2.4) C6(-4,-1.6) C7(-4,-0.8) C8(-4,0) C9(-4,0.8) C10(-4,1.6) C11(-4,2.4) C12(-4,3.2) C13(-4,4) C14(-4,4.8) C15(-4,5.6) D1(-3.2,-5.6) D2(-3.2,-4.8) D3(-3.2,-4) D4(-3.2,-3.2) D5(-3.2,-2.4) D6(-3.2,-1.6) D7(-3.2,-0.8) D8(-3.2,0) D9(-3.2,0.8) D10(-3.2,1.6) D11(-3.2,2.4) D12(-3.2,3.2) D13(-3.2,4) D14(-3.2,4.8) D15(-3.2,5.6) E1(-2.4,-5.6) E2(-2.4,-4.8) E3(-2.4,-4) E4(-2.4,-3.2) E5(-2.4,-2.4) E6(-2.4,-1.6) E7(-2.4,-0.8) E8(-2.4,0) E9(-2.4,0.8) E10(-2.4,1.6) E11(-2.4,2.4) E12(-2.4,3.2) E13(-2.4,4) E14(-2.4,4.8) E15(-2.4,5.6) F1(-1.6,-5.6) F2(-1.6,-4.8) F3(-1.6,-4) F4(-1.6,-3.2) F5(-1.6,-2.4) F6(-1.6,-1.6) F7(-1.6,-0.8) F8(-1.6,0) F9(-1.6,0.8) F10(-1.6,1.6) F11(-1.6,2.4) F12(-1.6,3.2) F13(-1.6,4) F14(-1.6,4.8) F15(-1.6,5.6) G1(-0.8,-5.6) G2(-0.8,-4.8) G3(-0.8,-4) G4(-0.8,-3.2) G5(-0.8,-2.4) G6(-0.8,-1.6) G7(-0.8,-0.8) G8(-0.8,0) G9(-0.8,0.8) G10(-0.8,1.6) G11(-0.8,2.4) G12(-0.8,3.2) G13(-0.8,4) G14(-0.8,4.8) G15(-0.8,5.6) H1(0,-5.6) H2(0,-4.8) H3(0,-4) H4(0,-3.2) H5(0,-2.4) H6(0,-1.6) H7(0,-0.8) H8(0,0) H9(0,0.8) H10(0,1.6) H11(0,2.4) H12(0,3.2) H13(0,4) H14(0,4.8) H15(0,5.6) J1(0.8,-5.6) J2(0.8,-4.8) J3(0.8,-4) J4(0.8,-3.2) J5(0.8,-2.4) J6(0.8,-1.6) J7(0.8,-0.8) J8(0.8,0) J9(0.8,0.8) J10(0.8,1.6) J11(0.8,2.4) J12(0.8,3.2) J13(0.8,4) J14(0.8,4.8) J15(0.8,5.6) K1(1.6,-5.6) K2(1.6,-4.8) K3(1.6,-4) K4(1.6,-3.2) K5(1.6,-2.4) K6(1.6,-1.6) K7(1.6,-0.8) K8(1.6,0) K9(1.6,0.8) K10(1.6,1.6) K11(1.6,2.4) K12(1.6,3.2) K13(1.6,4) K14(1.6,4.8) K15(1.6,5.6) L1(2.4,-5.6) L2(2.4,-4.8) L3(2.4,-4) L4(2.4,-3.2) L5(2.4,-2.4) L6(2.4,-1.6) L7(2.4,-0.8) L8(2.4,0) L9(2.4,0.8) L10(2.4,1.6) L11(2.4,2.4) L12(2.4,3.2) L13(2.4,4) L14(2.4,4.8) L15(2.4,5.6) M1(3.2,-5.6) M2(3.2,-4.8) M3(3.2,-4) M4(3.2,-3.2) M5(3.2,-2.4) M6(3.2,-1.6) M7(3.2,-0.8) M8(3.2,0) M9(3.2,0.8) M10(3.2,1.6) M11(3.2,2.4) M12(3.2,3.2) M13(3.2,4) M14(3.2,4.8) M15(3.2,5.6) N1(4,-5.6) N2(4,-4.8) N3(4,-4) N4(4,-3.2) N5(4,-2.4) N6(4,-1.6) N7(4,-0.8) N8(4,0) N9(4,0.8) N10(4,1.6) N11(4,2.4) N12(4,3.2) N13(4,4) N14(4,4.8) N15(4,5.6) P1(4.8,-5.6) P2(4.8,-4.8) P3(4.8,-4) P4(4.8,-3.2) P5(4.8,-2.4) P6(4.8,-1.6) P7(4.8,-0.8) P8(4.8,0) P9(4.8,0.8) P10(4.8,1.6) P11(4.8,2.4) P12(4.8,3.2) P13(4.8,4) P14(4.8,4.8) P15(4.8,5.6) R1(5.6,-5.6) R2(5.6,-4.8) R3(5.6,-4) R4(5.6,-3.2) R5(5.6,-2.4) R6(5.6,-1.6) R7(5.6,-0.8) R8(5.6,0) R9(5.6,0.8) R10(5.6,1.6) R11(5.6,2.4) R12(5.6,3.2) R13(5.6,4) R14(5.6,4.8) R15(5.6,5.6)
D0201
  rect 0.229x0.381 smd: A(0.22,0) C(-0.22,0)
DFN16_5X3_PAD4_4X1_65
  custom 0.165x0.165 smd: 1(-1.75,-1.43) 7(1.25,-1.43) 9(1.75,1.43) 15(-1.25,1.43)
  round 0.127 smd: 2(-1.25,-1.43) 8(1.75,-1.43) 10(1.25,1.43) 16(-1.75,1.43)
  rect 0.305x0.66 smd: 3(-0.75,-1.43) 4(-0.25,-1.43) 5(0.25,-1.43) 6(0.75,-1.43) 11(0.75,1.43) 12(0.25,1.43) 13(-0.25,1.43) 14(-0.75,1.43)
  rect 4.394x1.651 smd: PAD(0,0)
DO214AA
  rect 1.778x2.032 smd: A(2.311,0) C(-2.311,0)
F0805
  rect 0.991x1.499 smd: 1(-1.095,0) 2(1.095,0)
FBGA96_C
  round 0.381 smd: A1(-6,-3.2) A2(-6,-2.4) A3(-6,-1.6) A7(-6,1.6) A8(-6,2.4) A9(-6,3.2) B1(-5.2,-3.2) B2(-5.2,-2.4) B3(-5.2,-1.6) B7(-5.2,1.6) B8(-5.2,2.4) B9(-5.2,3.2) C1(-4.4,-3.2) C2(-4.4,-2.4) C3(-4.4,-1.6) C7(-4.4,1.6) C8(-4.4,2.4) C9(-4.4,3.2) D1(-3.6,-3.2) D2(-3.6,-2.4) D3(-3.6,-1.6) D7(-3.6,1.6) D8(-3.6,2.4) D9(-3.6,3.2) E1(-2.8,-3.2) E2(-2.8,-2.4) E3(-2.8,-1.6) E7(-2.8,1.6) E8(-2.8,2.4) E9(-2.8,3.2) F1(-2,-3.2) F2(-2,-2.4) F3(-2,-1.6) F7(-2,1.6) F8(-2,2.4) F9(-2,3.2) G1(-1.2,-3.2) G2(-1.2,-2.4) G3(-1.2,-1.6) G7(-1.2,1.6) G8(-1.2,2.4) G9(-1.2,3.2) H1(-0.4,-3.2) H2(-0.4,-2.4) H3(-0.4,-1.6) H7(-0.4,1.6) H8(-0.4,2.4) H9(-0.4,3.2) J1(0.4,-3.2) J2(0.4,-2.4) J3(0.4,-1.6) J7(0.4,1.6) J8(0.4,2.4) J9(0.4,3.2) K1(1.2,-3.2) K2(1.2,-2.4) K3(1.2,-1.6) K7(1.2,1.6) K8(1.2,2.4) K9(1.2,3.2) L1(2,-3.2) L2(2,-2.4) L3(2,-1.6) L7(2,1.6) L8(2,2.4) L9(2,3.2) M1(2.8,-3.2) M2(2.8,-2.4) M3(2.8,-1.6) M7(2.8,1.6) M8(2.8,2.4) M9(2.8,3.2) N1(3.6,-3.2) N2(3.6,-2.4) N3(3.6,-1.6) N7(3.6,1.6) N8(3.6,2.4) N9(3.6,3.2) P1(4.4,-3.2) P2(4.4,-2.4) P3(4.4,-1.6) P7(4.4,1.6) P8(4.4,2.4) P9(4.4,3.2) R1(5.2,-3.2) R2(5.2,-2.4) R3(5.2,-1.6) R7(5.2,1.6) R8(5.2,2.4) R9(5.2,3.2) T1(6,-3.2) T2(6,-2.4) T3(6,-1.6) T7(6,1.6) T8(6,2.4) T9(6,3.2)
L0402
  rect 0.584x0.711 smd: 1(-0.483,0) 2(0.483,0)
L0603
  rect 0.889x0.813 smd: 1(-0.737,0) 2(0.737,0)
L0805
  rect 1.143x1.27 smd: 1(-0.953,0) 2(0.953,0)
L0805-4PH39
  rect 0.889x0.406 smd: 1(-0.845,-0.403) 2(0.845,-0.403) 3(0.845,0.403) 4(-0.845,0.403)
L2020_A
  custom 0.425x0.425 smd: 1(-1.606,-1.501) 2(1.606,-1.501) 3(1.606,1.501) 4(-1.606,1.501)
L7144
  rect 0.635x1.016 smd: 1(-0.635,0) 2(0.635,0)
L9075
  rect 1.016x1.778 smd: 1(-0.889,0) 2(0.889,0)
LED0804
  rect 0.787x0.762 smd: A(1.1,0) C(-1.1,0)
LSMSQ79H41
  rect 1.041x2.21 smd: 1(-0.724,0) 2(0.724,0)
LSMSQ154H47_A
  custom 0.362x0.362 smd: 1(-1.765,0) 2(1.765,0)
LSMSQ157H47
  rect 0.965x3.404 smd: 1(-1.181,0) 2(1.181,0)
LSMSQ157H83
  rect 1.473x3.683 smd: 1(-1.232,0) 2(1.232,0)
LSMSQ157H122
  rect 0.965x3.708 smd: 1(-1.181,0) 2(1.181,0)
LSMSQ228H118_A
  custom 0.552x0.552 smd: 1(-2.682,0) 2(2.682,0)
LSMSQ287H161_A
  custom 0.629x0.629 smd: 1(-3.213,0) 2(3.213,0)
POWERDI323
  rect 0.864x0.737 smd: A(1.09,0)
  rect 1.753x1.016 smd: C(-0.65,0)
QFN8_3X3_PAD1_75X1_45
  oval 0.305x0.813 smd: 1(-0.75,-1.35) 2(-0.25,-1.35) 3(0.25,-1.35) 4(0.75,-1.35) 5(0.75,1.35) 6(0.25,1.35) 7(-0.25,1.35) 8(-0.75,1.35)
  rect 1.753x1.448 smd: PAD(0,0)
QFN8_3X3_PAD2_44X1_7
  oval 0.305x0.914 smd: 1(-0.75,-1.557) 2(-0.25,-1.557) 3(0.25,-1.557) 4(0.75,-1.557) 5(0.75,1.557) 6(0.25,1.557) 7(-0.25,1.557) 8(-0.75,1.557)
  rect 2.438x1.702 smd: PAD(0,0)
QFN10_3X3_PAD2_38X1_64
  oval 0.254x0.813 smd: 1(-1,-1.5) 2(-0.5,-1.5) 3(0,-1.5) 4(0.5,-1.5) 5(1,-1.5) 6(1,1.5) 7(0.5,1.5) 8(0,1.5) 9(-0.5,1.5) 10(-1,1.5)
  rect 2.388x1.651 smd: PAD(0,0)
QFN16_3X3_PAD1_7X1_7
  oval 0.305x0.787 smd: 1(-0.75,-1.5) 2(-0.25,-1.5) 3(0.25,-1.5) 4(0.75,-1.5) 9(0.75,1.5) 10(0.25,1.5) 11(-0.25,1.5) 12(-0.75,1.5)
  oval 0.787x0.305 smd: 5(1.5,-0.75) 6(1.5,-0.25) 7(1.5,0.25) 8(1.5,0.75) 13(-1.5,0.75) 14(-1.5,0.25) 15(-1.5,-0.25) 16(-1.5,-0.75)
  rect 1.702x1.702 smd: PAD(0,0)
QFN16_4X4_PAD2_5X2_5
  oval 0.356x0.991 smd: 1(-0.975,-1.974) 2(-0.325,-1.974) 3(0.325,-1.974) 4(0.975,-1.974) 9(0.975,1.974) 10(0.325,1.974) 11(-0.325,1.974) 12(-0.975,1.974)
  oval 0.991x0.356 smd: 5(1.974,-0.975) 6(1.974,-0.325) 7(1.974,0.325) 8(1.974,0.975) 13(-1.974,0.975) 14(-1.974,0.325) 15(-1.974,-0.325) 16(-1.974,-0.975)
  rect 2.489x2.489 smd: PAD(0,0)
QFN24_3_5X3_5_PAD2_2X2_2
  oval 0.203x0.813 smd: 1(-1,-1.75) 2(-0.6,-1.75) 3(-0.2,-1.75) 4(0.2,-1.75) 5(0.6,-1.75) 6(1,-1.75) 13(1,1.75) 14(0.6,1.75) 15(0.2,1.75) 16(-0.2,1.75) 17(-0.6,1.75) 18(-1,1.75)
  oval 0.813x0.203 smd: 7(1.75,-1) 8(1.75,-0.6) 9(1.75,-0.2) 10(1.75,0.2) 11(1.75,0.6) 12(1.75,1) 19(-1.75,1) 20(-1.75,0.6) 21(-1.75,0.2) 22(-1.75,-0.2) 23(-1.75,-0.6) 24(-1.75,-1)
  rect 2.21x2.21 smd: PAD(0,0)
QFN24_4X4_PAD2_3X2_3
  oval 0.305x0.991 smd: 1(-1.25,-2) 2(-0.75,-2) 3(-0.25,-2) 4(0.25,-2) 5(0.75,-2) 6(1.25,-2) 13(1.25,2) 14(0.75,2) 15(0.25,2) 16(-0.25,2) 17(-0.75,2) 18(-1.25,2)
  oval 0.991x0.305 smd: 7(2,-1.25) 8(2,-0.75) 9(2,-0.25) 10(2,0.25) 11(2,0.75) 12(2,1.25) 19(-2,1.25) 20(-2,0.75) 21(-2,0.25) 22(-2,-0.25) 23(-2,-0.75) 24(-2,-1.25)
  rect 2.311x2.311 smd: PAD(0,0)
QFN24_4X4_PAD2_5X2_5
  oval 0.305x0.991 smd: 1(-1.25,-2) 2(-0.75,-2) 3(-0.25,-2) 4(0.25,-2) 5(0.75,-2) 6(1.25,-2) 13(1.25,2) 14(0.75,2) 15(0.25,2) 16(-0.25,2) 17(-0.75,2) 18(-1.25,2)
  oval 0.991x0.305 smd: 7(2,-1.25) 8(2,-0.75) 9(2,-0.25) 10(2,0.25) 11(2,0.75) 12(2,1.25) 19(-2,1.25) 20(-2,0.75) 21(-2,0.25) 22(-2,-0.25) 23(-2,-0.75) 24(-2,-1.25)
  rect 2.489x2.489 smd: PAD(0,0)
QFN32_5X5_PAD3_1X3_1
  oval 0.305x0.889 smd: 1(-1.75,-2.45) 2(-1.25,-2.45) 3(-0.75,-2.45) 4(-0.25,-2.45) 5(0.25,-2.45) 6(0.75,-2.45) 7(1.25,-2.45) 8(1.75,-2.45) 17(1.75,2.45) 18(1.25,2.45) 19(0.75,2.45) 20(0.25,2.45) 21(-0.25,2.45) 22(-0.75,2.45) 23(-1.25,2.45) 24(-1.75,2.45)
  oval 0.889x0.305 smd: 9(2.45,-1.75) 10(2.45,-1.25) 11(2.45,-0.75) 12(2.45,-0.25) 13(2.45,0.25) 14(2.45,0.75) 15(2.45,1.25) 16(2.45,1.75) 25(-2.45,1.75) 26(-2.45,1.25) 27(-2.45,0.75) 28(-2.45,0.25) 29(-2.45,-0.25) 30(-2.45,-0.75) 31(-2.45,-1.25) 32(-2.45,-1.75)
  rect 3.099x3.099 smd: PAD(0,0)
QFN32_5X5_PAD3_3X3_3
  oval 0.305x0.889 smd: 1(-1.75,-2.45) 2(-1.25,-2.45) 3(-0.75,-2.45) 4(-0.25,-2.45) 5(0.25,-2.45) 6(0.75,-2.45) 7(1.25,-2.45) 8(1.75,-2.45) 17(1.75,2.45) 18(1.25,2.45) 19(0.75,2.45) 20(0.25,2.45) 21(-0.25,2.45) 22(-0.75,2.45) 23(-1.25,2.45) 24(-1.75,2.45)
  oval 0.889x0.305 smd: 9(2.45,-1.75) 10(2.45,-1.25) 11(2.45,-0.75) 12(2.45,-0.25) 13(2.45,0.25) 14(2.45,0.75) 15(2.45,1.25) 16(2.45,1.75) 25(-2.45,1.75) 26(-2.45,1.25) 27(-2.45,0.75) 28(-2.45,0.25) 29(-2.45,-0.25) 30(-2.45,-0.75) 31(-2.45,-1.25) 32(-2.45,-1.75)
  rect 3.302x3.302 smd: PAD(0,0)
QFN72_10X10_PAD7_1X7_1
  custom 0.07x0.07 smd: 1(-4.25,-4.845) 2(-3.75,-4.845) 3(-3.25,-4.845) 4(-2.75,-4.845) 5(-2.25,-4.845) 6(-1.75,-4.845) 7(-1.25,-4.845) 8(-0.75,-4.845) 9(-0.25,-4.845) 10(0.25,-4.845) 11(0.75,-4.845) 12(1.25,-4.845) 13(1.75,-4.845) 14(2.25,-4.845) 15(2.75,-4.845) 16(3.25,-4.845) 17(3.75,-4.845) 18(4.25,-4.845) 19(4.845,-4.25) 20(4.845,-3.75) 21(4.845,-3.25) 22(4.845,-2.75) 23(4.845,-2.25) 24(4.845,-1.75) 25(4.845,-1.25) 26(4.845,-0.75) 27(4.845,-0.25) 28(4.845,0.25) 29(4.845,0.75) 30(4.845,1.25) 31(4.845,1.75) 32(4.845,2.25) 33(4.845,2.75) 34(4.845,3.25) 35(4.845,3.75) 36(4.845,4.25) 37(4.25,4.845) 38(3.75,4.845) 39(3.25,4.845) 40(2.75,4.845) 41(2.25,4.845) 42(1.75,4.845) 43(1.25,4.845) 44(0.75,4.845) 45(0.25,4.845) 46(-0.25,4.845) 47(-0.75,4.845) 48(-1.25,4.845) 49(-1.75,4.845) 50(-2.25,4.845) 51(-2.75,4.845) 52(-3.25,4.845) 53(-3.75,4.845) 54(-4.25,4.845) 55(-4.845,4.25) 56(-4.845,3.75) 57(-4.845,3.25) 58(-4.845,2.75) 59(-4.845,2.25) 60(-4.845,1.75) 61(-4.845,1.25) 62(-4.845,0.75) 63(-4.845,0.25) 64(-4.845,-0.25) 65(-4.845,-0.75) 66(-4.845,-1.25) 67(-4.845,-1.75) 68(-4.845,-2.25) 69(-4.845,-2.75) 70(-4.845,-3.25) 71(-4.845,-3.75) 72(-4.845,-4.25)
  rect 7.112x7.112 smd: PAD(0,0)
R0201
  rect 0.305x0.406 smd: 1(-0.318,0) 2(0.318,0)
R0402
  rect 0.483x0.508 smd: 1(-0.43,0) 2(0.43,0)
R0402#2
  rect 0.559x0.61 smd: 1(-0.483,0) 2(0.483,0)
R0603
  rect 0.711x0.914 smd: 1(-0.6,0) 2(0.6,0)
R0603H35
  rect 0.813x0.813 smd: 1(-0.907,0) 2(0.907,0)
R0805
  rect 1.295x1.397 smd: 1(-0.953,0) 2(0.953,0)
R1206
  rect 1.6x1.6 smd: 1(-1.397,0) 2(1.397,0)
RM10
  rect 0.305x1.321 smd: 1(-1,-2.171) 2(-0.5,-2.171) 3(0,-2.171) 4(0.5,-2.171) 5(1,-2.171) 6(1,2.171) 7(0.5,2.171) 8(0,2.171) 9(-0.5,2.171) 10(-1,2.171)
SC70-6
  rect 0.406x0.508 smd: 1(-0.65,-0.95) 2(0,-0.95) 3(0.65,-0.95) 4(0.65,0.95) 5(0,0.95) 6(-0.65,0.95)
SC89
  rect 0.61x0.61 smd: 1(-0.5,-0.7) 2(0.5,-0.7) 3(0,0.7)
SO8
  rect 0.61x2.184 smd: 1(-1.905,-2.54) 2(-0.635,-2.54) 3(0.635,-2.54) 4(1.905,-2.54) 5(1.905,2.54) 6(0.635,2.54) 7(-0.635,2.54) 8(-1.905,2.54)
SOD123FL
  rect 0.914x1.219 smd: A(1.638,0) C(-1.638,0)
SON10_2X2_PAD1_5X0_9
  oval 0.203x0.762 smd: 1(-0.8,-1) 2(-0.4,-1) 3(0,-1) 4(0.4,-1) 5(0.8,-1) 6(0.8,1) 7(0.4,1) 8(0,1) 9(-0.4,1) 10(-0.8,1)
  rect 1.499x0.889 smd: PAD(0,0)
SOT23
  rect 1.016x1.397 smd: 1(-0.94,-1.118) 2(0.94,-1.118) 3(0,1.118)
SOT23-M3
  rect 0.787x0.889 smd: 1(-0.94,-1.003) 2(0.94,-1.003) 3(0,1.003)
SOT23_6-2
  rect 0.711x0.991 smd: 1(-0.95,-1.2) 2(0,-1.2) 3(0.95,-1.2) 4(0.95,1.2) 5(0,1.2) 6(-0.95,1.2)
SWSML140W138H55
  round 0.889 hole 0.711 unplated: (-0.9,0) (0.9,0)
  rect 1.041x1.397 smd: 1(-0.721,-1.799) 2(-0.721,1.799) 3(0.721,-1.799) 4(0.721,1.799)
  rect 0.508x1.092 smd: 5(-1.704,0)
TBGA24
  round 0.33 smd: A2(-2,-1) A3(-2,0) A4(-2,1) A5(-2,2) B1(-1,-2) B2(-1,-1) B3(-1,0) B4(-1,1) B5(-1,2) C1(0,-2) C2(0,-1) C3(0,0) C4(0,1) C5(0,2) D1(1,-2) D2(1,-1) D3(1,0) D4(1,1) D5(1,2) E1(2,-2) E2(2,-1) E3(2,0) E4(2,1) E5(2,2)
TPC50D30
  round 1.27 hole 0.762: 1(0,0)
TPSMC40
  round 1.016 smd: 1(0,0)
TSOT-5
  rect 0.508x1.524 smd: 1(-0.95,-1.17) 2(0,-1.17) 3(0.95,-1.17) 4(0.95,1.17) 5(-0.95,1.17)
TSSOP14
  rect 0.432x1.778 smd: 1(-1.95,-2.92) 2(-1.3,-2.92) 3(-0.65,-2.92) 4(0,-2.92) 5(0.65,-2.92) 6(1.3,-2.92) 7(1.95,-2.92) 8(1.95,2.92) 9(1.3,2.92) 10(0.65,2.92) 11(0,2.92) 12(-0.65,2.92) 13(-1.3,2.92) 14(-1.95,2.92)
TSSOP16
  rect 0.33x1.651 smd: 1(-2.275,-2.92) 2(-1.625,-2.92) 3(-0.975,-2.92) 4(-0.325,-2.92) 5(0.325,-2.92) 6(0.975,-2.92) 7(1.625,-2.92) 8(2.275,-2.92) 9(2.275,2.92) 10(1.625,2.92) 11(0.975,2.92) 12(0.325,2.92) 13(-0.325,2.92) 14(-0.975,2.92) 15(-1.625,2.92) 16(-2.275,2.92)
unnamed
  round 0.889 hole 0.635 unplated: (0,0)
WLCSP4-2
  round 0.254 smd: A1(-0.25,-0.25) A2(-0.25,0.25) B1(0.25,-0.25) B2(0.25,0.25)
YSML98W79H35
  rect 1.092x0.991 smd: 1(-0.921,-0.72) 2(0.921,-0.72) 3(0.921,0.72) 4(-0.921,0.72)
YSML197W126H59-2
  rect 1.6x1.295 smd: 1(-2,-1.248) 2(2,-1.248) 3(2,1.248) 4(-2,1.248)

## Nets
1.35V: C754.1 C758.1 E767.1 L520.2(N2) R763.1
1V0_D: C208.1 C241.1 E26.1 L9.2(N2) R207.1
1V8_A_1: C28.1 C33.1 C38.1 C43.1 C48.1 C53.1 C57.1 C61.1 E2.2(N2) R30.1 R56.1 U2.7 U2.8 U2.9
1V8_A_2: C25.1 C29.1 C34.1 C39.1 C45.1 C50.1 C54.1 C58.1 E3.2(N2) U2.53 U2.55
1V8_D: C20.1 C21.1 C31.1 C36.1 C41.1 C44.1 C49.1 C579.1 C589.1 C595.1 C596.1 C597.1 C598.1 C599.1 C656.1 C659.1 C664.1 C666.1 C668.1 C675.1 C676.1 C679.1 C683.1 C774.1 C788.1 C789.1 C790.1 C792.1 C793.1 C795.2(N2) C803.1 C805.1 C807.1 E2.1 E3.1 E677.1 E682.1 E768.2(N2) R145.1 R148.1 R584.1 R585.1 R586.1 R591.2(N2) R592.2(N2) R653.1 R681.1 R791.1 R798.1 U2.52 U508.B4 U511.A6 U511.B13 U511.C10 U511.D7 U511.E14 U511.H9 U511.J6 U511.J8 U511.K9 U511.L6 U524.8 U524.11 U524.14 U524.28 U524.30 U524.32 UNK1V8_D.1 Y523.4(VDD) Y578.4(VDD)
1V35: C600.1 C607.1 C614.1 C616.1 C617.1 C618.1 C626.1 C633.1 C637.1 C639.1 C641.1 C643.1 C645.1 C647.1 C649.1 C651.1 C652.1 C655.1 C658.1 C769.1 E767.2(N2) R635.2(N2) U509.1 U511.B3 U511.E4 U511.F1 U511.J2 U511.M3 U511.R4 U646.A1 U646.A8 U646.B2 U646.C1 U646.C9 U646.D2 U646.D9 U646.E9 U646.F1 U646.G7 U646.H2 U646.H9 U646.K2 U646.K8 U646.N1 U646.N9 U646.R1 U646.R9 UNK1V35.1
3V3_A: A11.8 A14.6 C14.1 C22.1 C47.1 C202.1 C204.1 C205.1 C206.1 C282.1 C284.1 C285.1 C286.1 C287.1 C298.1 C306.1 E8.2(N2) E9.1 E10.1 E12.1 R76.1 U18.3 U18.4 U19.3 U19.4 UNK3V3_A.1
3V3_A_1: C26.1 C30.1 C35.1 C40.1 C46.1 C51.1 C55.1 C59.1 R76.2(N2) U2.1 U2.58 U2.61 U2.67(TXVDD2)
3V3_AWG_A: A10.8 C242.1 C244.1 C246.1 C250.1 C253.1 E10.2(N2)
3V3_CLK_A: C224.1 C225.1 C226.1 C228.1 C229.1 C231.1 C232.1 C233.1 C234.1 C235.1 E12.2(N2) L15.2(N2) L16.2(N2) U14.2 U14.6(VVCO) U14.21 Y1.4(VCC)
3V3_D: C7.1 C27.1 C32.1 C37.1 C42.1 C60.1 C96.1 C240.1 C278.1 C299.1 C678.1 C696.1 C697.1 C698.1 C699.1 C700.1 C701.1 C702.1 C703.1 C704.1 C705.1 C706.1 C707.1 C708.1 C709.1 C710.1 C711.1 C712.1 C713.1 C801.1 E21.2(N2) P510.10(N5) R14.1 R87.1 R119.1 R130.1 R140.1 R142.1 R144.1 R155.1 R195.1 R196.1 R209.1 R210.1 R211.1 R216.1 R217.1 R685.2(N2) R689.2(N2) U2.20 U2.33 U2.51 U11.3 U15.18(VDD) U20.9 U511.F11 U511.G4 U511.H4 U511.H15 U511.J4 U511.J12 U511.K8 U511.M13 U511.N10 U511.P7 U511.R14 U524.20 U524.21 UNK3V3_D.1
3V3_D_LA: D2.2 D3.2 D4.2 D5.2 D6.2 D7.2 D8.2 D9.2 D10.2 D11.2 D12.2 D13.2 D14.2 D15.2 D16.2 D17.2 D18.2 D19.2 R209.2(N2)
3V3_SC_A: C105.1 C107.1 C109.1 C111.1 C113.1 C115.1 C117.1 C119.1 C154.1 C156.1 C158.1 C160.1 C164.1 C166.1 C168.1 C170.1 E9.2(N2) R47.1 U3.3 U3.4 U3.9 U3.10 U4.3 U4.4 U4.9 U4.10
4V0_A: A3.8 A5.8 C141.1 C142.1 C144.1 C311.1 C330.1 C331.1 C332.1 E1.2(N2) R164.1 U17.5 UNK4V0_A.1
5V0_A: C2.2(N2) C5.1 C18.1 C19.1 C177.1 C180.1 C310.1 E4.2(N2) L6.1 R68.2(N2) U7.1(VIN) U7.2 U10.12 U10.13 U17.1
6V0_A: C99.1 C101.1 C176.1 C212.1 C213.1 C214.1 E14.1 E17.1 E18.1 L7.2(N2) R73.2(N2) UNK6V0_A.1
6V0_AWG_A: A7.8 A9.8 A13.8 C258.1 C262.1 C264.1 C268.1 C270.1 C272.1 C274.1 C276.1 C300.1 C301.1 E17.2(N2) R201.1 R202.1
6V0_SC_A: A1.13 A2.13 A4.13 A6.8 A8.8 C78.1 C79.1 C80.1 C84.1 C86.1 C87.1 C135.1 C136.1 C137.1 C149.1 C150.1 C152.1 C288.1 C290.1 C294.1 C295.1 C333.1 C334.1 C335.1 E1.1 E14.2(N2) U8.11 U9.11
6V0_USR_A: A12.6 C314.1 C316.1 C318.1 C322.1 E18.2(N2)
-3V3_A: A11.4(V-) A11.PAD A12.2 C221.1 C222.1 C307.2(N2) C309.2(N2) C315.2(N2) C317.2(N2) C319.2(N2) C323.2(N2) E19.2(N2) E22.1 E24.1 R129.2(N2) UNK-3V3_A.1
-3V3_AWG_A: A10.4(V-) C243.2(N2) C245.2(N2) C247.2(N2) C251.2(N2) C254.2(N2) E24.2(N2)
-3V3_SC_A: C106.2(N2) C108.2(N2) C110.2(N2) C112.2(N2) C114.2(N2) C116.2(N2) C118.2(N2) C120.2(N2) C155.2(N2) C157.2(N2) C159.2(N2) C161.2(N2) C165.2(N2) C167.2(N2) C169.2(N2) C171.2(N2) E22.2(N2) R131.2(N2) U3.15 U3.16 U3.21 U3.22 U3.PAD U4.15 U4.16 U4.21 U4.22 U4.PAD
-5V0_SC_A: A3.4 A5.4 C98.1 C100.1 C102.1 C148.1 C151.1 C153.1 C329.1 E5.2(N2) VR1.5
-6V0_A: C9.1 C10.1 C11.1 C12.1 C209.1 C210.1 C211.1 C217.1 E13.1 E15.1 E16.1 L4.2(N2) R9.2(N2) R10.2(N2) U13.4 U13.7 U13.8 U13.PAD UNK-6V0_A.1
-6V0_AWG_A: A7.5(V-) A9.5(V-) C259.2(N2) C263.2(N2) C265.2(N2) C269.2(N2) C271.2(N2) C273.2(N2) C275.2(N2) C277.2(N2) E13.2(N2)
-6V0_SC_A: A1.4(VSS) A2.4(VSS) A4.4(VSS) C67.1 C68.1 C70.1 C81.1 C82.1 C83.1 C90.1 C91.1 C93.1 C124.1 C125.1 C127.1 C138.1 C139.1 C140.1 C327.1 E5.1 E15.2(N2) U8.1(VSS) U8.PAD U9.1(VSS) U9.PAD VR1.2
-6V0_USR_A: A14.2 C24.2(N2) C133.2(N2) C216.2(N2) C283.2(N2) E16.2(N2) R147.2(N2)
